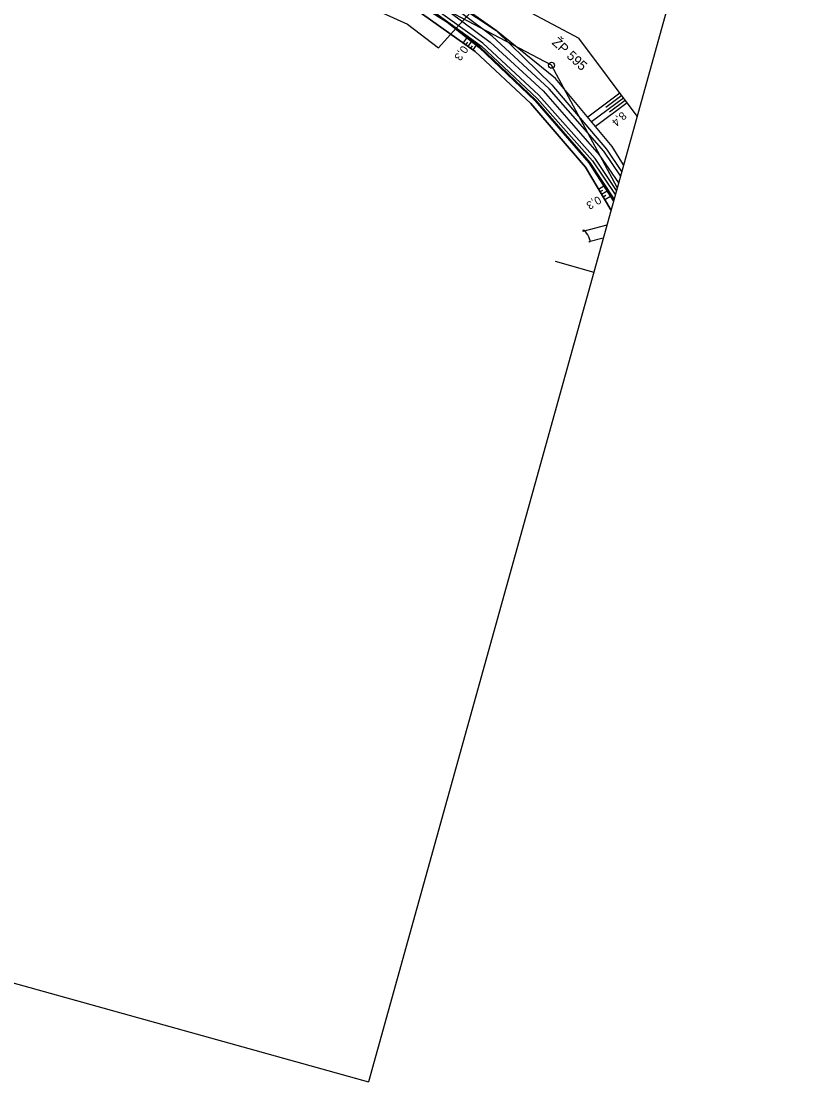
# Model space of a CAD drawing. Extents: x -795046 to -794647, y -1136002 to -1135518.
# Drawn here: x -794846.5 to -794647.1, y -1136002.2 to -1135737.2 of the extents above; entities that cross this region are included whole.
import ezdxf

# ---------------------------------------------------------------- set-up
doc = ezdxf.new("R2010")
doc.units = 0
for name, color, linetype in [('0381KM005-009P - Vrstva 1', 7, 'Continuous'), ('0381KM005-009P - Vrstva 13', 7, 'Continuous'), ('0381KM005-009P - Vrstva 18', 7, 'Continuous'), ('0381KM005-009P - Vrstva 4', 7, 'Continuous'), ('0381KM005-009P - Vrstva 48', 7, 'Continuous'), ('0381KM005-009P - Vrstva 49', 7, 'Continuous'), ('0381KM005-009P - Vrstva 51', 7, 'Continuous'), ('0381KM005-009P - Vrstva 55', 7, 'Continuous'), ('formát', 7, 'Continuous'), ('hran DP - hran DP', 7, 'Continuous'), ('vyt_sit - polygon', 7, 'Continuous'), ('vyt_sit - stávající', 7, 'Continuous')]:
    doc.layers.add(name, color=color, linetype=linetype)

msp = doc.modelspace()

# ---------------------------------------------------------------- linework, layer by layer
at = {"layer": '0381KM005-009P - Vrstva 1'}
msp.add_lwpolyline([(-794915, -1135523.08), (-794913.46, -1135539.92), (-794911.29, -1135554.01), (-794906.18, -1135575.42), (-794898.43, -1135596.89), (-794896.25, -1135601.39), (-794889.11, -1135615.73), (-794881.58, -1135627.73), (-794877.36, -1135634.16), (-794865.05, -1135649.67), (-794850.87, -1135664.43), (-794835.06, -1135677.82), (-794817.77, -1135689.58), (-794801.57, -1135698.91), (-794785.04, -1135707.72), (-794765.11, -1135718.4), (-794746.17, -1135729.82), (-794729.27, -1135742.41), (-794716.02, -1135754.58), (-794701.99, -1135770.6), (-794697.2, -1135777.62)], dxfattribs=at)
at = {"layer": '0381KM005-009P - Vrstva 13'}
for p, q in [((-794731.96, -1135743.53), (-794740.42, -1135737.03)), ((-794740.39, -1135737.12), (-794731.99, -1135743.74)), ((-794731.99, -1135743.74), (-794718, -1135757.13)), ((-794717.76, -1135757.03), (-794731.96, -1135743.53)), ((-794718, -1135757.13), (-794704.55, -1135772.63)), ((-794704.3, -1135772.51), (-794717.76, -1135757.03)), ((-794704.55, -1135772.63), (-794698.45, -1135782.11)), ((-794698.3, -1135781.58), (-794704.3, -1135772.51)), ((-794698.45, -1135782.11), (-794698.3, -1135781.58))]:
    msp.add_line(p, q, dxfattribs=at)
at = {"layer": '0381KM005-009P - Vrstva 18'}
for p, q in [((-794700.13, -1135788.16), (-794706.12, -1135789.75)), ((-794704.6, -1135792.28), (-794701, -1135791.3))]:
    msp.add_line(p, q, dxfattribs=at)
msp.add_ellipse((-794705.21, -1135790.89), major_axis=(-0.84, 1.43), ratio=0.263257, start_param=2.714626, end_param=6.783075, dxfattribs=at)
at = {"layer": '0381KM005-009P - Vrstva 4'}
for points in [[(-794917.47, -1135522.4), (-794915.85, -1135540.59), (-794913.67, -1135554.7), (-794908.27, -1135576.33), (-794900.49, -1135597.63), (-794890.98, -1135617.37), (-794879.27, -1135635.32), (-794866.44, -1135651.71), (-794836.69, -1135679.46), (-794818.84, -1135691.63), (-794786.57, -1135709.39), (-794766.3, -1135721.02), (-794748.58, -1135730.93), (-794731.42, -1135743.47), (-794717.51, -1135756.55), (-794703.68, -1135772.07), (-794698, -1135780.52)], [(-794697.72, -1135779.5), (-794703.02, -1135771.54), (-794717.11, -1135755.66), (-794731.12, -1135742.73), (-794748.15, -1135730.35), (-794763.88, -1135720.89), (-794786.11, -1135708.79), (-794818.08, -1135691.13), (-794836.08, -1135678.99), (-794851.61, -1135665.79), (-794866.22, -1135650.67), (-794878.82, -1135634.83), (-794890.24, -1135616.8), (-794899.85, -1135597.37), (-794907.59, -1135576.09), (-794912.87, -1135554.46), (-794914.85, -1135540.94), (-794916.58, -1135522.65)], [(-794696.7, -1135775.84), (-794700.88, -1135769.71), (-794714.51, -1135754.08), (-794728.76, -1135740.91), (-794743.23, -1135730.04), (-794762.73, -1135718.04), (-794783.1, -1135707.11), (-794816.84, -1135688.49), (-794833.24, -1135677.32), (-794850.38, -1135662.96), (-794864.1, -1135648.49), (-794876.22, -1135633.13), (-794886.94, -1135616.58), (-794897.05, -1135596.51), (-794904.69, -1135574.95), (-794909.82, -1135553.82), (-794912.02, -1135540.3), (-794913.51, -1135523.5)], [(-794912.74, -1135523.71), (-794911.32, -1135540.41), (-794909.07, -1135553.52), (-794904.05, -1135574.62), (-794896.27, -1135596.21), (-794886.26, -1135616.08), (-794875.38, -1135632.64), (-794863.5, -1135647.94), (-794849.93, -1135662.35), (-794832.65, -1135676.88), (-794816.85, -1135687.92), (-794782.78, -1135706.49), (-794762.23, -1135717.77), (-794742.47, -1135729.7), (-794727.73, -1135739.54), (-794713.83, -1135753.13), (-794700.2, -1135769.22), (-794696.4, -1135774.74)]]:
    msp.add_lwpolyline(points, dxfattribs=at)
at = {"layer": '0381KM005-009P - Vrstva 48'}
for p, q in [((-794735.95, -1135742.65), (-794735, -1135741.3)), ((-794735.34, -1135743.08), (-794734.87, -1135742.42)), ((-794734.72, -1135743.51), (-794733.82, -1135742.23)), ((-794734.11, -1135743.95), (-794733.67, -1135743.32)), ((-794733.5, -1135744.38), (-794732.64, -1135743.16)), ((-794696.83, -1135755.2), (-794704.87, -1135761.2)), ((-794696.38, -1135755.8), (-794700.39, -1135758.79)), ((-794695.94, -1135756.4), (-794703.91, -1135762.35)), ((-794695.04, -1135757.6), (-794702.95, -1135763.5)), ((-794695.49, -1135757), (-794699.46, -1135759.97)), ((-794702.17, -1135779.15), (-794700.85, -1135778.36)), ((-794701.79, -1135779.79), (-794701.12, -1135779.39)), ((-794701.41, -1135780.44), (-794700.04, -1135779.62)), ((-794701.02, -1135781.08), (-794700.33, -1135780.67)), ((-794700.64, -1135781.73), (-794699.22, -1135780.89))]:
    msp.add_line(p, q, dxfattribs=at)
at = {"layer": '0381KM005-009P - Vrstva 49'}
msp.add_line((-794692.56, -1135760.93), (-794707.09, -1135741.45), dxfattribs=at)
for points in [[(-794925.83, -1135520.07), (-794923.66, -1135547.6), (-794917.9, -1135570.81), (-794907.19, -1135600.69), (-794901.33, -1135612.99), (-794892.4, -1135627.36), (-794879.19, -1135644.46), (-794863.1, -1135661.78), (-794838.91, -1135683.03), (-794815.97, -1135701.12), (-794794.79, -1135715.61), (-794782.46, -1135721.1), (-794767.75, -1135725.5), (-794750.75, -1135732.17), (-794732.98, -1135744.75), (-794719.14, -1135757.73), (-794705.45, -1135773.64), (-794699.07, -1135784.37)], [(-794889.7, -1135608.37), (-794884.32, -1135618.22), (-794824.85, -1135679.44), (-794811.36, -1135687.77), (-794786.09, -1135699.38), (-794707.09, -1135741.45)], [(-794695.93, -1135773.08), (-794698.78, -1135768.51), (-794712.94, -1135751.52), (-794727.73, -1135739.54), (-794743.72, -1135728.23), (-794763.92, -1135716.02), (-794781.48, -1135706.54), (-794800.89, -1135696.32), (-794816.57, -1135687.28), (-794832.17, -1135676.47), (-794849.4, -1135661.77), (-794863.5, -1135647.94)], [(-794698.44, -1135782.1), (-794704.53, -1135772.61), (-794717.97, -1135757.09), (-794731.96, -1135743.69), (-794740.37, -1135737.09), (-794749.75, -1135730.99)]]:
    msp.add_lwpolyline(points, dxfattribs=at)
at = {"layer": '0381KM005-009P - Vrstva 51'}
msp.add_lwpolyline([(-794699.07, -1135784.37), (-794705.45, -1135773.64), (-794719.14, -1135757.73), (-794732.98, -1135744.75), (-794750.75, -1135732.17), (-794767.75, -1135725.5), (-794782.46, -1135721.1), (-794794.79, -1135715.61), (-794815.97, -1135701.12), (-794838.91, -1135683.03), (-794863.1, -1135661.78), (-794879.19, -1135644.46), (-794892.4, -1135627.36), (-794901.33, -1135612.99), (-794907.19, -1135600.69), (-794917.9, -1135570.81), (-794923.66, -1135547.6), (-794925.83, -1135520.07)], dxfattribs=at)
at = {"layer": '0381KM005-009P - Vrstva 55'}
msp.add_lwpolyline([(-794930.32, -1135518.82), (-794928.69, -1135543.86), (-794927.18, -1135552.03), (-794921.37, -1135573.41), (-794916.26, -1135587.98), (-794906.67, -1135609.69), (-794887.27, -1135641.42), (-794862.33, -1135667.74), (-794849.1, -1135679.42), (-794837.63, -1135688.88), (-794826.42, -1135697.51), (-794808.25, -1135711.35), (-794792.02, -1135721.49), (-794781.13, -1135725.75), (-794765.57, -1135730.81), (-794749.96, -1135737.95), (-794742.14, -1135743.85), (-794737.72, -1135738.96), (-794727.83, -1135728.01), (-794718.43, -1135717.37), (-794692.54, -1135688.86), (-794715.68, -1135650.06)], dxfattribs=at)
at = {"layer": 'formát'}
for p, q in [((-794647.13, -1135597.56), (-794703.39, -1135799.88)), ((-794713.02, -1135797.2), (-794703.39, -1135799.88)), ((-794713.02, -1135797.2), (-794703.39, -1135799.88)), ((-794703.39, -1135799.88), (-794759.64, -1136002.21)), ((-795045.79, -1135922.65), (-794759.64, -1136002.21)), ((-794769.27, -1135999.53), (-794759.64, -1136002.21))]:
    msp.add_line(p, q, dxfattribs=at)
at = {"layer": 'hran DP - hran DP'}
msp.add_line((-794737.72, -1135738.96), (-794755.22, -1135727.9), dxfattribs=at)
at = {"layer": 'vyt_sit - polygon'}
for p, q in [((-794713.93, -1135748.22), (-794813.55, -1135695.63)), ((-794697.51, -1135778.76), (-794713.93, -1135748.22))]:
    msp.add_line(p, q, dxfattribs=at)
at = {"layer": 'vyt_sit - stávající'}
msp.add_line((-794713.89, -1135748.25), (-794713.97, -1135748.19), dxfattribs=at)
msp.add_circle((-794713.93, -1135748.22), 0.756, dxfattribs=at)

# ---------------------------------------------------------------- texts
at = {"layer": '0381KM005-009P - Vrstva 48'}
for s, rotation, p in [('0,3', 234.7037, (-794736.2, -1135743.12)), ('8,4', 222.8696, (-794696.3, -1135759.67)), ('0,3', 210.7283, (-794702.25, -1135780.78))]:
    msp.add_text(s, height=2, rotation=rotation, dxfattribs=at).set_placement(p)
at = {"layer": 'vyt_sit - stávající'}
msp.add_text('ŽP 595', height=2.4, rotation=317.4103, dxfattribs=at).set_placement((-794714, -1135742.75))

doc.saveas('drawing.dxf')
